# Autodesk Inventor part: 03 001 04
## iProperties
Shininess: 64.0
Length Units: 11269
Angle Units: 11279
Time Units: 11290
Mass Units: 11283
Length Display Precision: 3
Angle Display Precision: 2
Compacted: True
Part Number: 03 001 04
Document SubType Name: Modeling
Created: 2003-12
Material: Standard
Designer: HAH
Manufacturer: Standard
Standards Organization: Custom
Description: Stütze
Density: 0.0
Volumn: 0.0
Area: 0.0
PropertySet Name: Model Information
Control State: 0
Master: False
Checked Out: False
Author: HAH
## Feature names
1. Extrusion1
